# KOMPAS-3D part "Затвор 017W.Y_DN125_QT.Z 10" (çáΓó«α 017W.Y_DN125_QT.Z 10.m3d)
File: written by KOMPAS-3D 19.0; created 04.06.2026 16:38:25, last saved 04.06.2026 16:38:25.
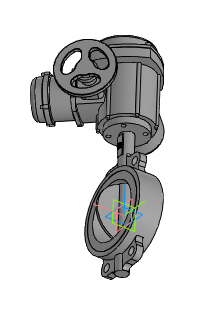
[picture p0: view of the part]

Document properties: Автор: Энергия; Полное имя файла: ..\..\..\3d для проектировщиков\017W разные\x.x Тип 017W.Y(S) Затвор дисковый поворотный межфланцевый\Затвор 017W.Y(S)_DN32-DN450_QT.Z\Затвор 017W.Y_DN125_QT.Z 10.a3d

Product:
- Part/product: Затвор 017W.Y_DN125_QT.Z 10
    Масса: 35.8984

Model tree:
1. Операция без истории:1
